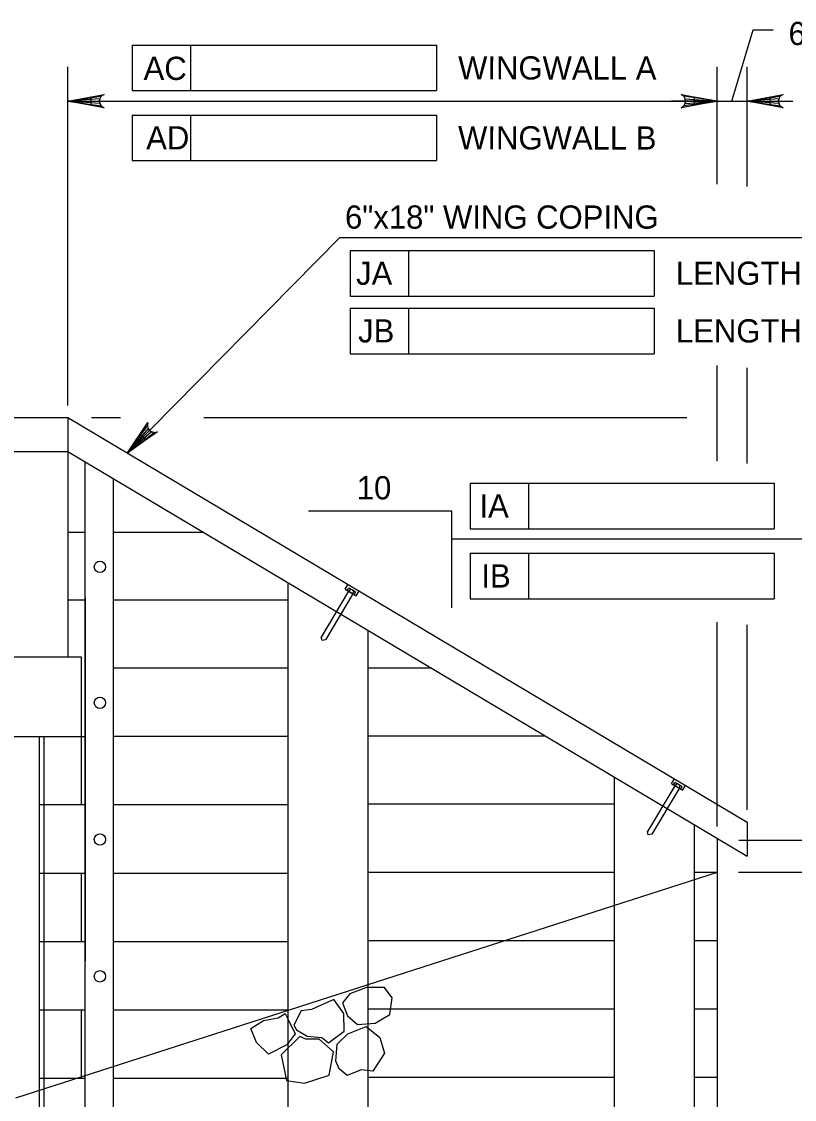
# Model space of a CAD drawing. Extents: x 638304 to 640306, y 296653 to 298435.
# Drawn here: x 638840 to 638939.9, y 297367 to 297506.3 of the extents above; entities that cross this region are included whole.
import ezdxf

# ---------------------------------------------------------------- set-up
doc = ezdxf.new("R2010")
doc.units = 0
for name, color, linetype in [('4', 7, 'Continuous'), ('Level 4', 7, 'Continuous'), ('Level 5', 7, 'Continuous')]:
    doc.layers.add(name, color=color, linetype=linetype)

# ---------------------------------------------------------------- blocks, each defined once
blk = doc.blocks.new('ROCK')
at = {"layer": '4'}
for points in [[(2.36725, 1.088), (2.2065, 0.82625), (2.378625, 0.506625), (2.66975, 0.3095), (3.128875, 0.403375), (3.48475, 0.6775), (3.4915, 1.123375), (3.25625, 1.36725), (2.783625, 1.308375)], [(1.10175, -0.02725), (1.4015, -0.159125), (1.78825, -0.148875), (1.980875, -0.266), (2.343375, 0.09475), (2.27875, 0.5505), (1.969375, 0.883), (1.4225, 0.553625), (1.152875, 0.479), (1.0105, 0.082)], [(0.74675, 0.359875), (0.882, 0.16), (1.072875, -0.144), (0.892, -0.457375), (0.448125, -0.758625), (0.1, -0.49325), (-0.095, -0.146375), (0.202875, 0.1025), (0.579125, 0.219875)], [(2.231375, -0.71725), (2.2025, -0.266375), (2.45475, 0.037125), (2.9085, 0.28875), (3.2995, 0.047625), (3.46875, -0.344), (3.231625, -0.855), (2.92, -0.860375), (2.5765, -1.054625), (2.340375, -0.904375)], [(1.2085, -0.192875), (0.778375, -0.737625), (1.008375, -1.391375), (1.48725, -1.396875), (2.09825, -1.106625), (2.133375, -0.486375), (1.723125, -0.203375), (1.37425, -0.239875)]]:
    blk.add_lwpolyline(points, close=True, dxfattribs=at)

msp = doc.modelspace()

# ---------------------------------------------------------------- linework, layer by layer
at = {"layer": 'Level 4'}
for p, q in [((638822.66, 297455.18), (638846.03, 297455.18)), ((638846.03, 297455.18), (638933.79, 297402.86)), ((638846.03, 297455.18), (638846.03, 297450.76)), ((638800.23, 297450.76), (638846.03, 297450.76)), ((638846.03, 297450.76), (638933.79, 297398.44)), ((638846.03, 297450.76), (638846.03, 297424.24)), ((638848.27, 297370.09), (638848.27, 297449.42)), ((638851.9, 297371.26), (638851.9, 297447.26)), ((638848.27, 297440.31), (638846.03, 297440.31)), ((638863.56, 297440.31), (638851.9, 297440.31)), ((638874.45, 297433.81), (638874.45, 297377.11)), ((638882.29, 297432.7), (638878.76, 297426.78)), ((638881.85, 297432.96), (638882.23, 297433.6)), ((638881.85, 297432.96), (638883.29, 297432.1)), ((638882.12, 297432.8), (638882.27, 297433.06)), ((638883.03, 297432.26), (638882.12, 297432.8)), ((638882.49, 297432.93), (638882.34, 297432.67)), ((638882.43, 297433.08), (638883.12, 297432.67)), ((638882.46, 297433.06), (638882.46, 297433.06)), ((638882.47, 297433.05), (638882.47, 297433.05)), ((638882.48, 297433.04), (638882.48, 297433.04)), ((638882.48, 297433.03), (638882.48, 297433.03)), ((638882.49, 297433.04), (638882.49, 297433.04)), ((638882.49, 297433.02), (638882.49, 297433.02)), ((638882.49, 297433), (638882.49, 297433)), ((638882.5, 297432.99), (638882.5, 297432.99)), ((638882.5, 297432.98), (638882.5, 297432.98)), ((638882.5, 297432.96), (638882.5, 297432.96)), ((638882.5, 297432.95), (638882.5, 297432.95)), ((638882.5, 297432.94), (638882.5, 297432.94)), ((638882.51, 297433.03), (638882.51, 297433.03)), ((638882.51, 297433.01), (638882.51, 297433.01)), ((638882.51, 297432.97), (638882.51, 297432.97)), ((638882.51, 297432.94), (638882.51, 297432.94)), ((638882.52, 297433.02), (638882.52, 297433.02)), ((638882.52, 297433), (638882.52, 297433)), ((638882.52, 297432.99), (638882.52, 297432.99)), ((638882.52, 297432.97), (638882.52, 297432.97)), ((638882.52, 297432.95), (638882.52, 297432.95)), ((638882.53, 297433.01), (638882.53, 297433.01)), ((638882.53, 297433), (638882.53, 297433)), ((638882.53, 297432.99), (638882.53, 297432.99)), ((638882.53, 297432.98), (638882.53, 297432.98)), ((638882.53, 297432.96), (638882.53, 297432.96)), ((638882.53, 297432.95), (638882.53, 297432.95)), ((638882.54, 297432.97), (638882.54, 297432.97)), ((638882.54, 297432.95), (638882.54, 297432.95)), ((638882.54, 297432.94), (638882.54, 297432.94)), ((638882.55, 297433), (638882.55, 297433)), ((638882.55, 297432.99), (638882.55, 297432.99)), ((638882.56, 297433), (638882.56, 297433)), ((638882.56, 297432.98), (638882.56, 297432.98)), ((638882.56, 297432.96), (638882.56, 297432.96)), ((638882.56, 297432.95), (638882.56, 297432.95)), ((638882.57, 297432.99), (638882.57, 297432.99)), ((638882.57, 297432.97), (638882.57, 297432.97)), ((638882.57, 297432.96), (638882.57, 297432.96)), ((638882.57, 297432.94), (638882.57, 297432.94)), ((638882.58, 297432.96), (638882.58, 297432.96)), ((638882.58, 297432.95), (638882.58, 297432.95)), ((638882.59, 297432.98), (638882.59, 297432.98)), ((638882.6, 297432.97), (638882.6, 297432.97)), ((638882.6, 297432.96), (638882.6, 297432.96)), ((638882.6, 297432.94), (638882.6, 297432.94)), ((638882.61, 297432.97), (638882.61, 297432.97)), ((638882.61, 297432.95), (638882.61, 297432.95)), ((638882.61, 297432.93), (638882.61, 297432.93)), ((638882.62, 297432.96), (638882.62, 297432.96)), ((638882.62, 297432.94), (638882.62, 297432.94)), ((638882.64, 297432.95), (638882.64, 297432.95)), ((638882.64, 297432.93), (638882.64, 297432.93)), ((638882.65, 297432.94), (638882.65, 297432.94)), ((638882.65, 297432.93), (638882.65, 297432.93)), ((638882.66, 297432.94), (638882.66, 297432.94)), ((638882.67, 297432.93), (638882.67, 297432.93)), ((638882.69, 297432.92), (638882.69, 297432.92)), ((638882.7, 297432.91), (638882.7, 297432.91)), ((638882.71, 297432.91), (638882.71, 297432.91)), ((638882.95, 297432.66), (638882.79, 297432.4)), ((638882.82, 297432.84), (638882.82, 297432.84)), ((638882.84, 297432.83), (638882.84, 297432.83)), ((638882.85, 297432.82), (638882.85, 297432.82)), ((638882.86, 297432.81), (638882.86, 297432.81)), ((638882.87, 297432.79), (638882.87, 297432.79)), ((638882.88, 297432.81), (638882.88, 297432.81)), ((638882.89, 297432.8), (638882.89, 297432.8)), ((638882.89, 297432.78), (638882.89, 297432.78)), ((638882.9, 297432.79), (638882.9, 297432.79)), ((638882.9, 297432.78), (638882.9, 297432.78)), ((638882.9, 297432.76), (638882.9, 297432.76)), ((638882.91, 297432.79), (638882.91, 297432.79)), ((638882.91, 297432.77), (638882.91, 297432.77)), ((638882.91, 297432.75), (638882.91, 297432.75)), ((638882.92, 297432.76), (638882.92, 297432.76)), ((638882.92, 297432.74), (638882.92, 297432.74)), ((638882.92, 297432.73), (638882.92, 297432.73)), ((638882.93, 297432.78), (638882.93, 297432.78)), ((638882.93, 297432.72), (638882.93, 297432.72)), ((638882.93, 297432.7), (638882.93, 297432.7)), ((638882.94, 297432.77), (638882.94, 297432.77)), ((638882.94, 297432.75), (638882.94, 297432.75)), ((638882.94, 297432.74), (638882.94, 297432.74)), ((638882.94, 297432.68), (638882.94, 297432.68)), ((638882.95, 297432.76), (638882.95, 297432.76)), ((638882.95, 297432.75), (638882.95, 297432.75)), ((638882.95, 297432.73), (638882.95, 297432.73)), ((638882.95, 297432.71), (638882.95, 297432.71)), ((638882.95, 297432.7), (638882.95, 297432.7)), ((638882.96, 297432.75), (638882.96, 297432.75)), ((638882.96, 297432.74), (638882.96, 297432.74)), ((638882.96, 297432.72), (638882.96, 297432.72)), ((638882.96, 297432.7), (638882.96, 297432.7)), ((638882.96, 297432.69), (638882.96, 297432.69)), ((638882.96, 297432.67), (638882.96, 297432.67)), ((638882.97, 297432.71), (638882.97, 297432.71)), ((638882.97, 297432.7), (638882.97, 297432.7)), ((638882.97, 297432.68), (638882.97, 297432.68)), ((638882.98, 297432.75), (638882.98, 297432.75)), ((638882.98, 297432.73), (638882.98, 297432.73)), ((638882.98, 297432.69), (638882.98, 297432.69)), ((638882.99, 297432.74), (638882.99, 297432.74)), ((638882.99, 297432.72), (638882.99, 297432.72)), ((638882.99, 297432.71), (638882.99, 297432.71)), ((638883, 297432.73), (638883, 297432.73)), ((638883, 297432.71), (638883, 297432.71)), ((638883, 297432.7), (638883, 297432.7)), ((638883.01, 297432.71), (638883.01, 297432.71)), ((638883.01, 297432.69), (638883.01, 297432.69)), ((638883.02, 297432.73), (638883.02, 297432.73)), ((638883.03, 297432.72), (638883.03, 297432.72)), ((638883.03, 297432.7), (638883.03, 297432.7)), ((638883.04, 297432.71), (638883.04, 297432.71)), ((638883.04, 297432.69), (638883.04, 297432.69)), ((638883.05, 297432.7), (638883.05, 297432.7)), ((638883.07, 297432.69), (638883.07, 297432.69)), ((638883.08, 297432.69), (638883.08, 297432.69)), ((638883.29, 297432.1), (638883.67, 297432.74)), ((638848.27, 297431.54), (638846.03, 297431.54)), ((638874.45, 297431.54), (638851.9, 297431.54)), ((638882.86, 297432.36), (638879.32, 297426.44)), ((638883.03, 297432.26), (638883.19, 297432.52)), ((638884.77, 297427.66), (638884.77, 297381.85)), ((638878.86, 297426.34), (638878.76, 297426.78)), ((638879.32, 297426.44), (638878.86, 297426.34)), ((638797.26, 297424.24), (638847.75, 297424.24)), ((638847.75, 297424.24), (638847.75, 297405.08)), ((638874.45, 297422.76), (638851.9, 297422.76)), ((638893.02, 297422.74), (638884.77, 297422.74)), ((638884.77, 297416.49), (638884.77, 297411.81)), ((638798.82, 297413.92), (638848.27, 297413.92)), ((638842.32, 297413.92), (638842.32, 297368.59)), ((638842.93, 297413.92), (638842.93, 297334.35)), ((638874.45, 297413.92), (638851.9, 297413.92)), ((638907.73, 297413.97), (638884.77, 297413.97)), ((638916.63, 297408.66), (638916.63, 297392.09)), ((638924.45, 297407.56), (638920.92, 297401.64)), ((638924.01, 297407.82), (638924.39, 297408.46)), ((638924.01, 297407.82), (638925.45, 297406.97)), ((638924.28, 297407.66), (638924.43, 297407.92)), ((638925.19, 297407.12), (638924.28, 297407.66)), ((638924.65, 297407.79), (638924.5, 297407.53)), ((638924.59, 297407.94), (638925.28, 297407.53)), ((638924.62, 297407.92), (638924.62, 297407.92)), ((638924.63, 297407.91), (638924.63, 297407.91)), ((638924.64, 297407.91), (638924.64, 297407.91)), ((638924.64, 297407.89), (638924.64, 297407.89)), ((638924.65, 297407.9), (638924.65, 297407.9)), ((638924.65, 297407.88), (638924.65, 297407.88)), ((638924.65, 297407.86), (638924.65, 297407.86)), ((638924.66, 297407.86), (638924.66, 297407.86)), ((638924.66, 297407.84), (638924.66, 297407.84)), ((638924.66, 297407.82), (638924.66, 297407.82)), ((638924.66, 297407.81), (638924.66, 297407.81)), ((638924.66, 297407.81), (638924.66, 297407.81)), ((638924.67, 297407.89), (638924.67, 297407.89)), ((638924.67, 297407.87), (638924.67, 297407.87)), ((638924.67, 297407.83), (638924.67, 297407.83)), ((638924.68, 297407.88), (638924.68, 297407.88)), ((638924.68, 297407.87), (638924.68, 297407.87)), ((638924.68, 297407.85), (638924.68, 297407.85)), ((638924.68, 297407.83), (638924.68, 297407.83)), ((638924.68, 297407.82), (638924.68, 297407.82)), ((638924.68, 297407.8), (638924.68, 297407.8)), ((638924.69, 297407.87), (638924.69, 297407.87)), ((638924.69, 297407.86), (638924.69, 297407.86)), ((638924.69, 297407.86), (638924.69, 297407.86)), ((638924.69, 297407.84), (638924.69, 297407.84)), ((638924.69, 297407.82), (638924.69, 297407.82)), ((638924.69, 297407.81), (638924.69, 297407.81)), ((638924.7, 297407.87), (638924.7, 297407.87)), ((638924.7, 297407.85), (638924.7, 297407.85)), ((638924.7, 297407.83), (638924.7, 297407.83)), ((638924.7, 297407.82), (638924.7, 297407.82)), ((638924.7, 297407.8), (638924.7, 297407.8)), ((638924.72, 297407.86), (638924.72, 297407.86)), ((638924.72, 297407.84), (638924.72, 297407.84)), ((638924.72, 297407.82), (638924.72, 297407.82)), ((638924.72, 297407.81), (638924.72, 297407.81)), ((638924.73, 297407.85), (638924.73, 297407.85)), ((638924.73, 297407.84), (638924.73, 297407.84)), ((638924.73, 297407.82), (638924.73, 297407.82)), ((638924.73, 297407.8), (638924.73, 297407.8)), ((638924.74, 297407.84), (638924.74, 297407.84)), ((638924.74, 297407.83), (638924.74, 297407.83)), ((638924.74, 297407.81), (638924.74, 297407.81)), ((638924.75, 297407.82), (638924.75, 297407.82)), ((638924.75, 297407.8), (638924.75, 297407.8)), ((638924.76, 297407.84), (638924.76, 297407.84)), ((638924.77, 297407.83), (638924.77, 297407.83)), ((638924.77, 297407.81), (638924.77, 297407.81)), ((638924.77, 297407.8), (638924.77, 297407.8)), ((638924.78, 297407.82), (638924.78, 297407.82)), ((638924.78, 297407.8), (638924.78, 297407.8)), ((638924.79, 297407.81), (638924.79, 297407.81)), ((638924.79, 297407.8), (638924.79, 297407.8)), ((638924.81, 297407.81), (638924.81, 297407.81)), ((638924.81, 297407.79), (638924.81, 297407.79)), ((638924.82, 297407.8), (638924.82, 297407.8)), ((638924.83, 297407.79), (638924.83, 297407.79)), ((638924.84, 297407.78), (638924.84, 297407.78)), ((638924.86, 297407.78), (638924.86, 297407.78)), ((638924.87, 297407.77), (638924.87, 297407.77)), ((638925.11, 297407.52), (638924.95, 297407.26)), ((638924.99, 297407.7), (638924.99, 297407.7)), ((638925, 297407.69), (638925, 297407.69)), ((638925.01, 297407.69), (638925.01, 297407.69)), ((638925.02, 297407.68), (638925.02, 297407.68)), ((638925.03, 297407.65), (638925.03, 297407.65)), ((638925.04, 297407.67), (638925.04, 297407.67)), ((638925.05, 297407.66), (638925.05, 297407.66)), ((638925.05, 297407.65), (638925.05, 297407.65)), ((638925.06, 297407.65), (638925.06, 297407.65)), ((638925.06, 297407.64), (638925.06, 297407.64)), ((638925.06, 297407.62), (638925.06, 297407.62)), ((638925.07, 297407.65), (638925.07, 297407.65)), ((638925.07, 297407.63), (638925.07, 297407.63)), ((638925.07, 297407.61), (638925.07, 297407.61)), ((638925.08, 297407.62), (638925.08, 297407.62)), ((638925.08, 297407.61), (638925.08, 297407.61)), ((638925.08, 297407.59), (638925.08, 297407.59)), ((638925.09, 297407.64), (638925.09, 297407.64)), ((638925.09, 297407.58), (638925.09, 297407.58)), ((638925.09, 297407.57), (638925.09, 297407.57)), ((638925.1, 297407.63), (638925.1, 297407.63)), ((638925.1, 297407.61), (638925.1, 297407.61)), ((638925.1, 297407.6), (638925.1, 297407.6)), ((638925.1, 297407.54), (638925.1, 297407.54)), ((638925.11, 297407.63), (638925.11, 297407.63)), ((638925.11, 297407.61), (638925.11, 297407.61)), ((638925.11, 297407.59), (638925.11, 297407.59)), ((638925.11, 297407.58), (638925.11, 297407.58)), ((638925.11, 297407.56), (638925.11, 297407.56)), ((638925.12, 297407.62), (638925.12, 297407.62)), ((638925.12, 297407.6), (638925.12, 297407.6)), ((638925.12, 297407.58), (638925.12, 297407.58)), ((638925.12, 297407.57), (638925.12, 297407.57)), ((638925.12, 297407.55), (638925.12, 297407.55)), ((638925.12, 297407.54), (638925.12, 297407.54)), ((638925.13, 297407.58), (638925.13, 297407.58)), ((638925.13, 297407.56), (638925.13, 297407.56)), ((638925.13, 297407.54), (638925.13, 297407.54)), ((638925.14, 297407.61), (638925.14, 297407.61)), ((638925.14, 297407.59), (638925.14, 297407.59)), ((638925.15, 297407.6), (638925.15, 297407.6)), ((638925.15, 297407.59), (638925.15, 297407.59)), ((638925.15, 297407.57), (638925.15, 297407.57)), ((638925.15, 297407.55), (638925.15, 297407.55)), ((638925.16, 297407.59), (638925.16, 297407.59)), ((638925.16, 297407.58), (638925.16, 297407.58)), ((638925.16, 297407.56), (638925.16, 297407.56)), ((638925.17, 297407.59), (638925.17, 297407.59)), ((638925.17, 297407.57), (638925.17, 297407.57)), ((638925.17, 297407.55), (638925.17, 297407.55)), ((638925.19, 297407.58), (638925.19, 297407.58)), ((638925.19, 297407.56), (638925.19, 297407.56)), ((638925.2, 297407.57), (638925.2, 297407.57)), ((638925.2, 297407.55), (638925.2, 297407.55)), ((638925.21, 297407.57), (638925.21, 297407.57)), ((638925.22, 297407.56), (638925.22, 297407.56)), ((638925.24, 297407.55), (638925.24, 297407.55)), ((638925.45, 297406.97), (638925.83, 297407.6)), ((638925.01, 297407.22), (638921.48, 297401.3)), ((638925.19, 297407.12), (638925.35, 297407.38)), ((638848.27, 297405.08), (638842.32, 297405.08)), ((638874.45, 297405.08), (638851.9, 297405.08)), ((638916.63, 297405.2), (638884.77, 297405.2)), ((638926.95, 297402.51), (638926.95, 297395.46)), ((638933.79, 297402.86), (638933.79, 297398.44)), ((638921.02, 297401.2), (638920.92, 297401.64)), ((638921.48, 297401.3), (638921.02, 297401.2)), ((638929.9, 297400.76), (638929.9, 297396.36)), ((638929.9, 297396.36), (638839.27, 297367.19)), ((638916.63, 297396.36), (638884.77, 297396.36)), ((638929.9, 297396.36), (638926.95, 297396.36)), ((638929.9, 297396.36), (638929.9, 297334.47)), ((638848.27, 297396.24), (638842.32, 297396.24)), ((638847.75, 297396.24), (638847.75, 297387.4)), ((638874.45, 297396.24), (638851.9, 297396.24)), ((638926.95, 297395.53), (638926.95, 297323.03)), ((638916.63, 297392.09), (638916.63, 297322.76)), ((638848.27, 297387.4), (638842.32, 297387.4)), ((638874.45, 297387.4), (638851.9, 297387.4)), ((638902.42, 297387.52), (638884.77, 297387.52)), ((638916.64, 297387.52), (638902.42, 297387.52)), ((638929.9, 297387.52), (638926.95, 297387.52)), ((638884.77, 297381.85), (638884.77, 297323.03)), ((638848.27, 297378.56), (638842.32, 297378.56)), ((638847.75, 297378.56), (638847.75, 297369.71)), ((638874.45, 297378.56), (638851.9, 297378.56)), ((638916.63, 297378.67), (638884.77, 297378.67)), ((638929.9, 297378.67), (638926.95, 297378.67)), ((638874.45, 297377.11), (638874.45, 297322.76)), ((638851.9, 297334.35), (638851.9, 297371.26)), ((638848.27, 297334.35), (638848.27, 297370.09)), ((638848.27, 297369.71), (638842.32, 297369.71)), ((638842.32, 297368.59), (638842.32, 297322.64)), ((638874.45, 297369.71), (638851.9, 297369.71)), ((638916.63, 297369.83), (638884.77, 297369.83)), ((638929.9, 297369.83), (638926.95, 297369.83))]:
    msp.add_line(p, q, dxfattribs=at)
for centre in [(638850.16, 297435.85), (638850.16, 297418.29), (638850.16, 297400.61), (638850.16, 297382.93)]:
    msp.add_circle(centre, 0.737, dxfattribs=at)
for centre, radius, start, end in [((638882.36, 297432.96), 0.134, 346.6464, 131.7428), ((638882.55, 297432.51), 0.423, 20.2446, 98.1446), ((638883.04, 297432.54), 0.148, 61.0217, 127.9076), ((638883.04, 297432.54), 0.148, 350.4815, 61.0216), ((638924.52, 297407.83), 0.134, 346.6464, 131.7428), ((638924.71, 297407.38), 0.423, 20.2446, 98.1446), ((638925.2, 297407.41), 0.148, 61.0217, 127.9076), ((638925.2, 297407.41), 0.148, 350.4815, 61.0216)]:
    msp.add_arc(centre, radius, start, end, dxfattribs=at)
at = {"layer": 'Level 5'}
for p, q in [((638931.82, 297496.06), (638934.58, 297505.27)), ((638934.58, 297505.27), (638937.17, 297505.27)), ((638854.33, 297503.31), (638854.33, 297497.41)), ((638854.33, 297503.31), (638893.63, 297503.31)), ((638861.88, 297503.31), (638861.88, 297497.41)), ((638893.63, 297503.31), (638893.63, 297497.41)), ((638846.03, 297456.71), (638846.03, 297500.48)), ((638929.9, 297485.33), (638929.9, 297500.48)), ((638933.79, 297485), (638933.79, 297500.48)), ((638854.33, 297497.41), (638893.63, 297497.41)), ((638846.03, 297496.06), (638929.9, 297496.06)), ((638926.95, 297496.06), (638924, 297496.06)), ((638929.9, 297496.06), (638937.68, 297496.06)), ((638933.79, 297496.06), (638939.68, 297496.06)), ((638854.33, 297494.26), (638893.63, 297494.26)), ((638854.33, 297494.26), (638854.33, 297488.37)), ((638861.88, 297494.26), (638861.88, 297488.37)), ((638893.63, 297494.26), (638893.63, 297488.37)), ((638854.33, 297488.37), (638893.63, 297488.37)), ((638853.71, 297450.6), (638881.18, 297478.41)), ((638881.18, 297478.41), (638974.68, 297478.41)), ((638882.48, 297476.76), (638882.48, 297470.86)), ((638882.48, 297476.76), (638921.77, 297476.76)), ((638890.03, 297476.76), (638890.03, 297470.86)), ((638921.77, 297476.76), (638921.77, 297470.86)), ((638882.48, 297470.86), (638921.77, 297470.86)), ((638882.48, 297469.31), (638921.77, 297469.31)), ((638882.48, 297469.31), (638882.48, 297463.41)), ((638890.03, 297469.31), (638890.03, 297463.41)), ((638921.77, 297469.31), (638921.77, 297463.41)), ((638882.48, 297463.41), (638921.77, 297463.41)), ((638929.9, 297449.53), (638929.9, 297461.9)), ((638933.79, 297449.21), (638933.79, 297461.57)), ((638849.07, 297455.18), (638852.82, 297455.18)), ((638863.57, 297455.18), (638925.98, 297455.18)), ((638897.99, 297446.67), (638937.29, 297446.67)), ((638897.99, 297446.67), (638897.99, 297440.78)), ((638905.54, 297446.67), (638905.54, 297440.78)), ((638937.29, 297446.67), (638937.29, 297440.78)), ((638895.65, 297443.07), (638877.1, 297443.07)), ((638895.65, 297430.56), (638895.65, 297443.07)), ((638897.99, 297440.78), (638937.29, 297440.78)), ((638970.34, 297439.42), (638895.65, 297439.42)), ((638897.99, 297437.63), (638897.99, 297431.74)), ((638897.99, 297437.63), (638937.29, 297437.63)), ((638905.54, 297437.63), (638905.54, 297431.74)), ((638937.29, 297437.63), (638937.29, 297431.74)), ((638848.27, 297431.87), (638848.27, 297384.88)), ((638897.99, 297431.74), (638937.29, 297431.74)), ((638929.9, 297402.29), (638929.9, 297428.71)), ((638933.79, 297404.44), (638933.79, 297428.38)), ((638932.72, 297400.54), (639033.98, 297400.54)), ((638940.93, 297396.36), (638932.66, 297396.36))]:
    msp.add_line(p, q, dxfattribs=at)
for points in [[(638846.03, 297496.06), (638850.69, 297496.93), (638850.33, 297496.68), (638850.14, 297496.37), (638850.09, 297496.06), (638850.14, 297495.75), (638850.33, 297495.43), (638850.69, 297495.19), (638846.03, 297496.06), (638850.33, 297495.43), (638850.14, 297495.75), (638846.03, 297496.06), (638850.09, 297496.06), (638850.14, 297496.37), (638846.03, 297496.06), (638850.33, 297496.68)], [(638929.9, 297496.06), (638925.25, 297495.19), (638925.6, 297495.43), (638925.79, 297495.75), (638925.84, 297496.06), (638925.79, 297496.37), (638925.6, 297496.68), (638925.25, 297496.93), (638929.9, 297496.06), (638925.6, 297496.68), (638925.79, 297496.37), (638929.9, 297496.06), (638925.84, 297496.06), (638925.79, 297495.75), (638929.9, 297496.06), (638925.6, 297495.43)], [(638933.79, 297496.06), (638938.44, 297496.93), (638938.08, 297496.68), (638937.9, 297496.37), (638937.84, 297496.06), (638937.9, 297495.75), (638938.08, 297495.43), (638938.44, 297495.19), (638933.79, 297496.06), (638938.08, 297495.43), (638937.9, 297495.75), (638933.79, 297496.06), (638937.84, 297496.06), (638937.9, 297496.37), (638933.79, 297496.06), (638938.08, 297496.68)], [(638853.71, 297450.6), (638856.36, 297454.52), (638856.29, 297454.09), (638856.38, 297453.74), (638856.56, 297453.49), (638856.82, 297453.3), (638857.17, 297453.22), (638857.6, 297453.3), (638853.71, 297450.6), (638857.17, 297453.22), (638856.82, 297453.3), (638853.71, 297450.6), (638856.56, 297453.49), (638856.38, 297453.74), (638853.71, 297450.6), (638856.29, 297454.09)]]:
    msp.add_lwpolyline(points, dxfattribs=at)
for points in [[(638848.98, 297496.55), (638848.98, 297495.57), (638846.03, 297496.06)], [(638926.95, 297496.55), (638926.95, 297495.57), (638929.9, 297496.06)], [(638936.74, 297496.55), (638936.74, 297495.57), (638933.79, 297496.06)], [(638856.04, 297452.28), (638855.36, 297452.95), (638853.71, 297450.6)]]:
    msp.add_lwpolyline(points, close=True, dxfattribs=at)

# ---------------------------------------------------------------- block references
at = {"layer": 'Level 5', "xscale": 4.911876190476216, "yscale": 4.911876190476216, "rotation": -7.30063298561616}
msp.add_blockref('ROCK', (638870.23, 297376.85), dxfattribs=at)

# ---------------------------------------------------------------- texts
at = {"layer": 'Level 5'}
for s, height, p in [('6"', 3, (638939.14, 297503.3)), ('6"x18" WING COPING', 3.0001, (638881.83, 297479.57)), ('JA', 3, (638883.26, 297472.31)), ('LENGTH WINGWALL A', 3.0001, (638924.59, 297472.31)), ('JB', 3, (638883.52, 297464.86)), ('LENGTH WINGWALL B', 3.0001, (638924.59, 297464.86)), ('10', 3, (638883.35, 297444.58))]:
    msp.add_text(s, height=height, dxfattribs=at).set_placement(p)
for s, p in [('AC', (638855.8, 297498.8)), ('WINGWALL A', (638896.44, 297498.86)), ('AD', (638856.14, 297489.82)), ('WINGWALL B', (638896.44, 297489.82)), ('IA', (638899.2, 297442.23)), ('IB', (638899.45, 297433.18))]:
    msp.add_text(s, height=3, rotation=359.9382, dxfattribs=at).set_placement(p)

doc.saveas('drawing.dxf')
